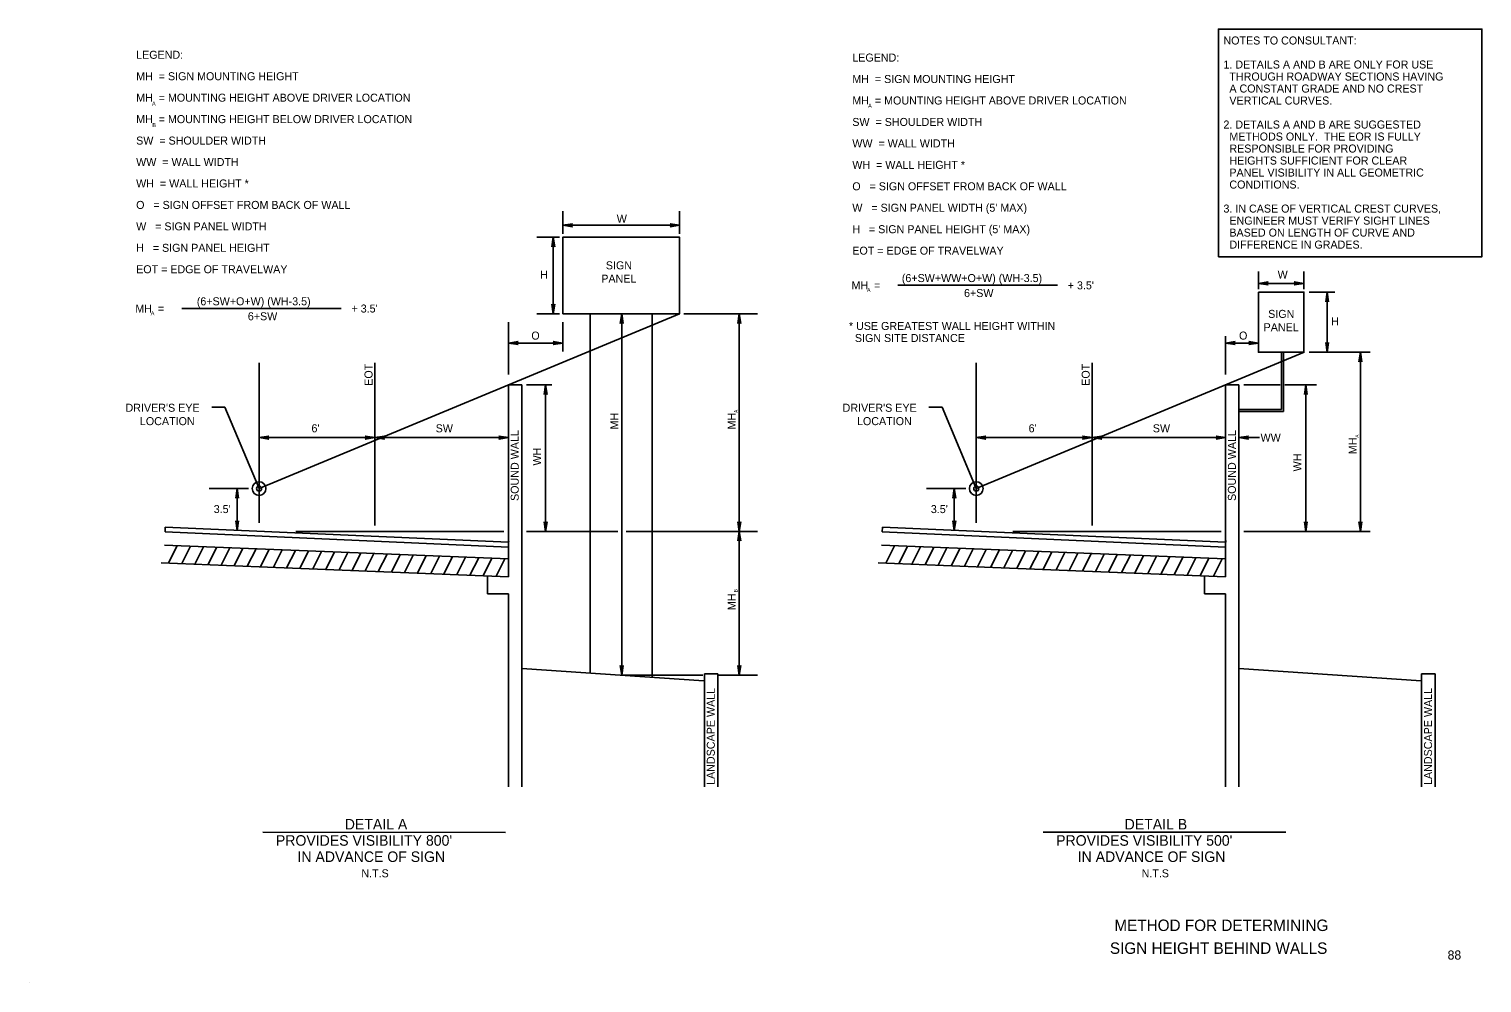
# Model space of a CAD drawing. Extents: x -863 to -227, y -614 to -197.
import ezdxf

# ---------------------------------------------------------------- set-up
doc = ezdxf.new("R2010")
doc.units = 0
for name, color, linetype in [('AdhocPoint_dp', 7, 'Continuous'), ('AsphaltMisc', 7, 'Continuous'), ('Base_px', 7, 'Continuous'), ('DimLines_dp', 7, 'Continuous'), ('TextAlert', 7, 'Continuous'), ('TextDetails', 7, 'Continuous'), ('TextGeotech', 7, 'Continuous'), ('TextLabel', 7, 'Continuous'), ('TextMisc', 7, 'Continuous'), ('TextNotes', 7, 'Continuous'), ('TextShtNo', 7, 'Continuous')]:
    doc.layers.add(name, color=color, linetype=linetype)

msp = doc.modelspace()

# ---------------------------------------------------------------- linework, layer by layer
at = {"layer": 'AdhocPoint_dp'}
msp.add_line((-862.51, -614.11), (-862.51, -614.11), dxfattribs=at)
at = {"layer": 'AsphaltMisc'}
for p, q in [((-802.9, -414.8), (-802.96, -416.83)), ((-802.96, -416.83), (-652.79, -423.57)), ((-652.79, -421.4), (-802.9, -414.8)), ((-489.2, -414.82), (-489.27, -416.84)), ((-489.27, -416.84), (-339.06, -423.58)), ((-339.06, -421.41), (-489.2, -414.82)), ((-652.79, -423.57), (-652.79, -421.4)), ((-339.06, -423.58), (-339.06, -421.41))]:
    msp.add_line(p, q, dxfattribs=at)
at = {"layer": 'Base_px'}
for p, q in [((-577.91, -321.45), (-761.88, -397.92)), ((-617.03, -478.62), (-617.03, -321.45)), ((-589.93, -480.42), (-589.93, -321.45)), ((-304.74, -338.3), (-448.17, -397.92)), ((-314.68, -363.31), (-314.68, -338.3)), ((-313.77, -364.22), (-313.77, -338.3)), ((-652.79, -436.45), (-652.79, -352.57)), ((-652.79, -352.57), (-647, -352.57)), ((-647, -528.36), (-647, -352.57)), ((-339.06, -436.47), (-339.06, -352.57)), ((-339.06, -352.57), (-333.26, -352.57)), ((-333.26, -528.4), (-333.26, -352.57)), ((-333.26, -363.31), (-314.68, -363.31)), ((-333.26, -364.22), (-313.77, -364.22)), ((-803.27, -422.64), (-711.23, -426.32)), ((-801.48, -430.51), (-797.66, -422.87)), ((-795.74, -430.74), (-791.92, -423.1)), ((-790, -430.97), (-786.18, -423.33)), ((-784.26, -431.2), (-780.44, -423.56)), ((-778.52, -431.43), (-774.7, -423.78)), ((-772.78, -431.66), (-768.96, -424.01)), ((-767.04, -431.88), (-763.22, -424.24)), ((-761.3, -432.11), (-757.48, -424.47)), ((-755.57, -432.34), (-751.75, -424.7)), ((-749.84, -432.57), (-746.02, -424.93)), ((-744.11, -432.8), (-740.29, -425.16)), ((-738.38, -433.03), (-734.56, -425.39)), ((-732.65, -433.26), (-728.83, -425.62)), ((-489.58, -422.65), (-397.51, -426.34)), ((-487.78, -430.52), (-483.96, -422.88)), ((-482.04, -430.75), (-478.22, -423.11)), ((-476.3, -430.98), (-472.48, -423.34)), ((-470.56, -431.21), (-466.74, -423.57)), ((-464.82, -431.44), (-461, -423.8)), ((-459.08, -431.67), (-455.26, -424.03)), ((-453.34, -431.9), (-449.52, -424.26)), ((-447.6, -432.13), (-443.77, -424.49)), ((-441.87, -432.36), (-438.04, -424.72)), ((-436.13, -432.59), (-432.31, -424.94)), ((-430.4, -432.82), (-426.58, -425.17)), ((-424.67, -433.05), (-420.85, -425.4)), ((-418.94, -433.28), (-415.12, -425.63)), ((-804.73, -430.38), (-761.88, -432.09)), ((-761.88, -432.09), (-652.79, -436.45)), ((-726.92, -433.49), (-723.1, -425.85)), ((-721.2, -433.72), (-717.38, -426.08)), ((-715.47, -433.95), (-711.65, -426.31)), ((-711.23, -426.32), (-652.79, -428.66)), ((-709.74, -434.18), (-705.92, -426.54)), ((-704.01, -434.41), (-700.19, -426.77)), ((-698.28, -434.64), (-694.46, -426.99)), ((-692.55, -434.86), (-688.73, -427.22)), ((-686.82, -435.09), (-683, -427.45)), ((-681.09, -435.32), (-677.27, -427.68)), ((-675.36, -435.55), (-671.54, -427.91)), ((-669.63, -435.78), (-665.81, -428.14)), ((-663.9, -436.01), (-660.08, -428.37)), ((-658.17, -436.24), (-654.35, -428.6)), ((-491.04, -430.39), (-448.17, -432.11)), ((-448.17, -432.11), (-339.06, -436.47)), ((-413.21, -433.5), (-409.39, -425.86)), ((-407.48, -433.73), (-403.66, -426.09)), ((-401.75, -433.96), (-397.93, -426.32)), ((-397.51, -426.34), (-339.06, -428.68)), ((-396.02, -434.19), (-392.2, -426.55)), ((-390.29, -434.42), (-386.47, -426.78)), ((-384.56, -434.65), (-380.74, -427.01)), ((-378.83, -434.88), (-375, -427.24)), ((-373.09, -435.11), (-369.27, -427.47)), ((-367.36, -435.34), (-363.54, -427.7)), ((-361.63, -435.57), (-357.81, -427.92)), ((-355.9, -435.8), (-352.08, -428.15)), ((-350.17, -436.03), (-346.35, -428.38)), ((-344.44, -436.26), (-340.62, -428.61)), ((-661.99, -432.19), (-661.99, -432.19)), ((-661.99, -432.19), (-661.99, -432.19)), ((-661.99, -436.09), (-661.99, -443.98)), ((-348.26, -432.2), (-348.26, -432.2)), ((-348.26, -432.2), (-348.26, -432.2)), ((-348.26, -436.1), (-348.26, -444)), ((-661.99, -443.98), (-652.79, -443.98)), ((-652.79, -443.98), (-652.79, -528.36)), ((-348.26, -444), (-339.06, -444)), ((-339.06, -444), (-339.06, -528.4)), ((-647, -476.64), (-567.31, -481.92)), ((-333.26, -476.66), (-253.55, -481.95)), ((-567.07, -528.36), (-567.07, -478.86)), ((-567.07, -478.86), (-561.18, -478.86)), ((-561.18, -528.36), (-561.18, -478.86)), ((-253.32, -528.4), (-253.32, -478.88)), ((-253.32, -478.88), (-247.42, -478.88)), ((-247.42, -528.4), (-247.42, -478.88))]:
    msp.add_line(p, q, dxfattribs=at)
for points in [[(-629.05, -321.45), (-577.91, -321.45), (-577.91, -287.99), (-629.05, -287.99)], [(-324.74, -312), (-304.86, -312), (-304.86, -338.3), (-324.74, -338.3)]]:
    msp.add_lwpolyline(points, close=True, dxfattribs=at)
for centre in [(-652.55, -421.4), (-338.81, -421.41)]:
    msp.add_ellipse(centre, major_axis=(0, 0.487), ratio=0.5, start_param=6.189709, end_param=7.853982, dxfattribs=at)
at = {"layer": 'DimLines_dp'}
for p, q in [((-629.05, -286.53), (-629.05, -276.59)), ((-577.91, -286.53), (-577.91, -276.59)), ((-624.84, -282.15), (-629.05, -282.78)), ((-577.91, -282.78), (-629.05, -282.78)), ((-629.05, -282.78), (-624.84, -283.41)), ((-625.68, -282.78), (-624.84, -282.15)), ((-624.84, -283.41), (-625.68, -282.78)), ((-577.91, -282.78), (-582.12, -282.15)), ((-582.12, -282.15), (-581.28, -282.78)), ((-581.28, -282.78), (-582.12, -283.41)), ((-582.12, -283.41), (-577.91, -282.78)), ((-630.5, -287.99), (-640.44, -287.99)), ((-633.17, -287.99), (-633.8, -292.19)), ((-633.8, -292.19), (-633.17, -291.35)), ((-633.17, -321.45), (-633.17, -287.99)), ((-632.54, -292.19), (-633.17, -287.99)), ((-633.17, -291.35), (-632.54, -292.19)), ((-324.74, -310.7), (-324.74, -302.97)), ((-304.86, -310.7), (-304.86, -302.97)), ((-320.53, -307.54), (-324.74, -308.17)), ((-304.86, -308.17), (-324.74, -308.17)), ((-324.74, -308.17), (-320.53, -308.8)), ((-321.37, -308.17), (-320.53, -307.54)), ((-320.53, -308.8), (-321.37, -308.17)), ((-304.86, -308.17), (-309.07, -307.54)), ((-309.07, -307.54), (-308.23, -308.17)), ((-308.23, -308.17), (-309.07, -308.8)), ((-309.07, -308.8), (-304.86, -308.17)), ((-633.17, -318.08), (-633.8, -317.24)), ((-633.8, -317.24), (-633.17, -321.45)), ((-633.17, -321.45), (-632.54, -317.24)), ((-632.54, -317.24), (-633.17, -318.08)), ((-291.36, -312), (-302.53, -312)), ((-294.65, -312), (-295.28, -316.2)), ((-295.28, -316.2), (-294.65, -315.36)), ((-294.65, -338.3), (-294.65, -312)), ((-294.02, -316.2), (-294.65, -312)), ((-294.65, -315.36), (-294.02, -316.2)), ((-630.5, -321.45), (-640.44, -321.45)), ((-603.23, -321.45), (-603.86, -325.65)), ((-603.23, -479.54), (-603.23, -321.45)), ((-602.6, -325.65), (-603.23, -321.45)), ((-576.08, -321.45), (-543.91, -321.45)), ((-551.81, -321.45), (-552.45, -325.65)), ((-551.81, -416.61), (-551.81, -321.45)), ((-551.18, -325.65), (-551.81, -321.45)), ((-652.79, -348.05), (-652.79, -325.2)), ((-629.05, -325.2), (-629.05, -338.03)), ((-603.86, -325.65), (-603.23, -324.81)), ((-603.23, -324.81), (-602.6, -325.65)), ((-552.45, -325.65), (-551.81, -324.81)), ((-551.81, -324.81), (-551.18, -325.65)), ((-648.58, -333.64), (-652.79, -334.27)), ((-629.05, -334.27), (-652.79, -334.27)), ((-652.79, -334.27), (-648.58, -334.9)), ((-649.43, -334.27), (-648.58, -333.64)), ((-648.58, -334.9), (-649.43, -334.27)), ((-629.05, -334.27), (-633.25, -333.64)), ((-633.25, -333.64), (-632.41, -334.27)), ((-632.41, -334.27), (-633.25, -334.9)), ((-633.25, -334.9), (-629.05, -334.27)), ((-339.06, -348.04), (-339.06, -331.19)), ((-334.85, -333.63), (-339.06, -334.26)), ((-324.74, -334.26), (-339.06, -334.26)), ((-339.06, -334.26), (-334.85, -334.89)), ((-335.69, -334.26), (-334.85, -333.63)), ((-334.85, -334.89), (-335.69, -334.26)), ((-324.74, -334.26), (-328.95, -333.63)), ((-328.95, -333.63), (-328.11, -334.26)), ((-328.11, -334.26), (-328.95, -334.89)), ((-328.95, -334.89), (-324.74, -334.26)), ((-294.65, -334.93), (-295.28, -334.09)), ((-295.28, -334.09), (-294.65, -338.3)), ((-294.65, -338.3), (-294.02, -334.09)), ((-294.02, -334.09), (-294.65, -334.93)), ((-761.88, -412.85), (-761.88, -342.91)), ((-711.23, -414.1), (-711.23, -342.91)), ((-448.17, -412.86), (-448.17, -342.9)), ((-397.51, -414.11), (-397.51, -342.9)), ((-275.88, -338.3), (-302.53, -338.3)), ((-280.11, -338.3), (-280.74, -342.51)), ((-280.74, -342.51), (-280.11, -341.67)), ((-280.11, -416.62), (-280.11, -338.3)), ((-279.48, -342.51), (-280.11, -338.3)), ((-280.11, -341.67), (-279.48, -342.51)), ((-633.8, -352.57), (-644.87, -352.57)), ((-636.53, -352.57), (-637.17, -356.78)), ((-636.53, -416.61), (-636.53, -352.57)), ((-635.9, -356.78), (-636.53, -352.57)), ((-315.2, -352.57), (-331.13, -352.57)), ((-299.28, -352.57), (-313.21, -352.57)), ((-303.99, -352.57), (-304.62, -356.78)), ((-303.99, -416.62), (-303.99, -352.57)), ((-303.35, -356.78), (-303.99, -352.57)), ((-637.17, -356.78), (-636.53, -355.94)), ((-636.53, -355.94), (-635.9, -356.78)), ((-304.62, -356.78), (-303.99, -355.93)), ((-303.99, -355.93), (-303.35, -356.78)), ((-782.61, -362.37), (-776.82, -362.37)), ((-776.82, -362.37), (-761.88, -397.92)), ((-468.91, -362.37), (-463.12, -362.37)), ((-463.12, -362.37), (-448.17, -397.92)), ((-757.67, -375), (-761.88, -375.64)), ((-761.88, -375.64), (-757.67, -376.27)), ((-761.88, -375.64), (-652.79, -375.64)), ((-758.51, -375.64), (-757.67, -375)), ((-757.67, -376.27), (-758.51, -375.64)), ((-714.6, -375.64), (-715.44, -375)), ((-715.44, -375), (-711.23, -375.64)), ((-711.23, -375.64), (-715.44, -376.27)), ((-715.44, -376.27), (-714.6, -375.64)), ((-707.02, -375), (-711.23, -375.64)), ((-711.23, -375.64), (-707.02, -376.27)), ((-707.87, -375.64), (-707.02, -375)), ((-707.02, -376.27), (-707.87, -375.64)), ((-652.79, -375.64), (-657, -375)), ((-657, -375), (-656.16, -375.64)), ((-656.16, -375.64), (-657, -376.27)), ((-657, -376.27), (-652.79, -375.64)), ((-443.96, -375), (-448.17, -375.64)), ((-448.17, -375.64), (-443.96, -376.27)), ((-448.17, -375.64), (-339.06, -375.64)), ((-444.81, -375.64), (-443.96, -375)), ((-443.96, -376.27), (-444.81, -375.64)), ((-400.88, -375.64), (-401.72, -375)), ((-401.72, -375), (-397.51, -375.64)), ((-397.51, -375.64), (-401.72, -376.27)), ((-401.72, -376.27), (-400.88, -375.64)), ((-393.3, -375), (-397.51, -375.64)), ((-397.51, -375.64), (-393.3, -376.27)), ((-394.15, -375.64), (-393.3, -375)), ((-393.3, -376.27), (-394.15, -375.64)), ((-339.06, -375.64), (-343.27, -375)), ((-343.27, -375), (-342.43, -375.64)), ((-342.43, -375.64), (-343.27, -376.27)), ((-343.27, -376.27), (-339.06, -375.64)), ((-329.05, -375), (-333.26, -375.64)), ((-333.26, -375.64), (-324.28, -375.64)), ((-333.26, -375.64), (-329.05, -376.27)), ((-329.89, -375.64), (-329.05, -375)), ((-329.05, -376.27), (-329.89, -375.64)), ((-766.49, -397.92), (-783.7, -397.92)), ((-772.13, -402.13), (-771.5, -397.92)), ((-771.5, -416.19), (-771.5, -397.92)), ((-771.5, -397.92), (-770.86, -402.13)), ((-452.78, -397.92), (-470, -397.92)), ((-458.42, -402.13), (-457.79, -397.92)), ((-457.79, -416.2), (-457.79, -397.92)), ((-457.79, -397.92), (-457.16, -402.13)), ((-771.5, -401.28), (-772.13, -402.13)), ((-770.86, -402.13), (-771.5, -401.28)), ((-457.79, -401.29), (-458.42, -402.13)), ((-457.16, -402.13), (-457.79, -401.29)), ((-771.5, -412.82), (-772.13, -411.98)), ((-772.13, -411.98), (-771.5, -416.19)), ((-771.5, -416.19), (-770.86, -411.98)), ((-770.86, -411.98), (-771.5, -412.82)), ((-636.53, -413.24), (-637.17, -412.4)), ((-637.17, -412.4), (-636.53, -416.61)), ((-636.53, -416.61), (-635.9, -412.4)), ((-635.9, -412.4), (-636.53, -413.24)), ((-551.81, -413.24), (-552.45, -412.4)), ((-552.45, -412.4), (-551.81, -416.61)), ((-551.81, -416.61), (-551.18, -412.4)), ((-551.18, -412.4), (-551.81, -413.24)), ((-457.79, -412.83), (-458.42, -411.99)), ((-458.42, -411.99), (-457.79, -416.2)), ((-457.79, -416.2), (-457.16, -411.99)), ((-457.16, -411.99), (-457.79, -412.83)), ((-303.99, -413.25), (-304.62, -412.41)), ((-304.62, -412.41), (-303.99, -416.62)), ((-303.99, -416.62), (-303.35, -412.41)), ((-303.35, -412.41), (-303.99, -413.25)), ((-280.11, -413.25), (-280.74, -412.41)), ((-280.74, -412.41), (-280.11, -416.62)), ((-280.11, -416.62), (-279.48, -412.41)), ((-279.48, -412.41), (-280.11, -413.25)), ((-654.81, -416.61), (-745.83, -416.61)), ((-604.88, -416.61), (-644.87, -416.61)), ((-543.91, -416.61), (-601.28, -416.61)), ((-551.81, -416.61), (-552.45, -420.82)), ((-551.81, -479.54), (-551.81, -416.61)), ((-551.18, -420.82), (-551.81, -416.61)), ((-341.07, -416.62), (-432.12, -416.62)), ((-275.88, -416.62), (-331.13, -416.62)), ((-552.45, -420.82), (-551.81, -419.97)), ((-551.81, -419.97), (-551.18, -420.82)), ((-603.23, -476.17), (-603.86, -475.33)), ((-603.86, -475.33), (-603.23, -479.54)), ((-603.23, -479.54), (-602.6, -475.33)), ((-602.6, -475.33), (-603.23, -476.17)), ((-551.81, -476.17), (-552.45, -475.33)), ((-552.45, -475.33), (-551.81, -479.54)), ((-551.81, -479.54), (-551.18, -475.33)), ((-551.18, -475.33), (-551.81, -476.17)), ((-567.76, -479.53), (-603.23, -479.53)), ((-543.91, -479.53), (-560.72, -479.53))]:
    msp.add_line(p, q, dxfattribs=at)
for centre, radius in [((-761.88, -397.92), 2.98), ((-761.88, -397.92), 1.12), ((-448.17, -397.92), 2.98), ((-448.17, -397.92), 1.12)]:
    msp.add_circle(centre, radius, dxfattribs=at)
at = {"layer": 'TextAlert'}
msp.add_lwpolyline([(-342.24, -296.54), (-226.95, -296.54), (-226.95, -196.95), (-342.24, -196.95)], close=True, dxfattribs=at)
at = {"layer": 'TextDetails'}
for p, q in [((-760.2, -548.13), (-654.02, -548.31)), ((-418.87, -548.13), (-312.7, -548.13))]:
    msp.add_line(p, q, dxfattribs=at)
at = {"layer": 'TextGeotech'}
for centre in [(-652.55, -421.4), (-338.81, -421.41)]:
    msp.add_ellipse(centre, major_axis=(0, -0.487), ratio=0.5, start_param=2.956245, end_param=4.712389, dxfattribs=at)
at = {"layer": 'TextLabel'}
for p, q in [((-482.4, -309.01), (-412.67, -309.01)), ((-795.69, -319.16), (-725.97, -319.16))]:
    msp.add_line(p, q, dxfattribs=at)

# ---------------------------------------------------------------- texts
at = {"layer": 'DimLines_dp'}
for s, height, p in [('EOT', 3.506, (-712.25, -352.96)), ('EOT', 3.507, (-398.53, -352.95)), ('MH', 3.506, (-604.72, -372.04)), ('MH', 3.506, (-553.38, -372.04)), ('A', 1.5, (-552.6, -364.81)), ('SOUND WALL', 3.506, (-648.31, -403.34)), ('SOUND WALL', 3.507, (-334.58, -403.34)), ('A', 1.5, (-280.89, -375.67)), ('WH', 3.506, (-638.51, -387.82)), ('MH', 3.507, (-281.68, -382.9)), ('WH', 3.507, (-305.96, -390.41)), ('MH', 3.506, (-553.38, -451.09)), ('B', 1.5, (-552.6, -443.28)), ('LANDSCAPE WALL', 3.5064, (-562.54, -527.52)), ('LANDSCAPE WALL', 3.5073, (-248.78, -527.56))]:
    msp.add_text(s, height=height, rotation=90, dxfattribs=at).set_placement(p)
at = {"layer": 'TextAlert'}
for s, p in [('NOTES TO CONSULTANT:', (-340.03, -203.7)), ('1. DETAILS A AND B ARE ONLY FOR USE', (-340.03, -214.2)), ('  THROUGH ROADWAY SECTIONS HAVING', (-340.03, -219.45)), ('  A CONSTANT GRADE AND NO CREST', (-340.03, -224.7)), ('  VERTICAL CURVES.', (-340.03, -229.95)), ('2. DETAILS A AND B ARE SUGGESTED', (-340.03, -240.45)), ('  METHODS ONLY.  THE EOR IS FULLY', (-340.03, -245.7)), ('  RESPONSIBLE FOR PROVIDING', (-340.03, -250.95)), ('  HEIGHTS SUFFICIENT FOR CLEAR ', (-340.03, -256.2)), ('  PANEL VISIBILITY IN ALL GEOMETRIC', (-340.03, -261.45)), ('  CONDITIONS.', (-340.03, -266.7)), ('3. IN CASE OF VERTICAL CREST CURVES,', (-340.03, -277.21)), ('  ENGINEER MUST VERIFY SIGHT LINES', (-340.03, -282.46)), ('  BASED ON LENGTH OF CURVE AND', (-340.03, -287.71)), ('  DIFFERENCE IN GRADES.', (-340.03, -292.96))]:
    msp.add_text(s, height=3.5006, dxfattribs=at).set_placement(p)
at = {"layer": 'TextDetails'}
for s, height, p in [('DETAIL A', 4.6, (-724.4, -547)), ('DETAIL B', 4.6, (-383.24, -547)), ("PROVIDES VISIBILITY 800'", 4.6, (-754.53, -554.1)), ("PROVIDES VISIBILITY 500'", 4.6, (-413.21, -554.1)), ('IN ADVANCE OF SIGN', 4.6, (-745.1, -561.2)), ('IN ADVANCE OF SIGN', 4.6, (-403.78, -561.2)), ('N.T.S', 3.5, (-717.14, -567.91)), ('N.T.S', 3.5, (-375.82, -567.91))]:
    msp.add_text(s, height=height, dxfattribs=at).set_placement(p)
at = {"layer": 'TextLabel'}
for s, height, p in [('(6+SW+WW+O+W) (WH-3.5)', 3.5006, (-480.72, -307.6)), ('MH  = ', 3.501, (-502.73, -310.76)), ('A', 1.75, (-495.99, -311.99)), ('6+SW', 3.501, (-453.51, -314.16)), ("+ 3.5'", 3.501, (-408.15, -310.77)), ('MH  = ', 3.5, (-816.02, -320.91)), ('(6+SW+O+W) (WH-3.5)', 3.4996, (-789.13, -317.75)), ("+ 3.5'", 3.5, (-721.46, -320.92)), ('A', 1.75, (-809.28, -322.14)), ('6+SW', 3.5, (-766.81, -324.31)), ('* USE GREATEST WALL HEIGHT WITHIN', 3.5006, (-503.86, -328.55)), ('  SIGN SITE DISTANCE', 3.5006, (-503.86, -333.8))]:
    msp.add_text(s, height=height, dxfattribs=at).set_placement(p)
at = {"layer": 'TextMisc'}
for s, height, p in [('W', 3.51, (-605.42, -281.68)), ('SIGN', 3.506, (-610.2, -302.03)), ('H', 3.51, (-639, -306.1)), ('PANEL', 3.506, (-612.19, -307.87)), ('W', 3.51, (-316.33, -306.05)), ('SIGN', 3.507, (-320.47, -323.27)), ('H', 3.51, (-292.91, -326.57)), ('O', 3.51, (-642.79, -332.77)), ('O', 3.51, (-333.2, -332.76)), ('PANEL', 3.507, (-322.46, -329.11)), ("DRIVER'S EYE", 3.5064, (-820.32, -364.32)), ("DRIVER'S EYE", 3.5073, (-506.63, -364.32)), ('LOCATION', 3.506, (-814.03, -370.17)), ('LOCATION', 3.507, (-500.34, -370.17)), ("6'", 3.506, (-738.97, -373.3)), ('SW', 3.506, (-684.64, -373.3)), ("6'", 3.507, (-425.26, -373.3)), ('SW', 3.507, (-370.92, -373.3)), ('WW', 3.507, (-323.8, -377.37)), ("3.5'", 3.506, (-781.73, -408.62)), ("3.5'", 3.507, (-468.03, -408.63))]:
    msp.add_text(s, height=height, dxfattribs=at).set_placement(p)
for s, p in [(' METHOD FOR DETERMINING ', (-389.61, -591.4)), ('SIGN HEIGHT BEHIND WALLS', (-389.7, -601.4))]:
    msp.add_text(s, height=5, rotation=360, dxfattribs=at).set_placement(p)
at = {"layer": 'TextNotes'}
for s, height, p in [('LEGEND:', 3.5, (-815.66, -209.95)), ('LEGEND:', 3.501, (-502.38, -211.17)), ('MH  = SIGN MOUNTING HEIGHT', 3.4996, (-815.66, -219.33)), ('MH  = SIGN MOUNTING HEIGHT', 3.5006, (-502.38, -220.55)), ('MH  = MOUNTING HEIGHT ABOVE DRIVER LOCATION', 3.4996, (-815.66, -228.71)), ('A', 1.75, (-808.75, -230.4)), ('MH  = MOUNTING HEIGHT ABOVE DRIVER LOCATION', 3.5006, (-502.38, -229.94)), ('MH  = MOUNTING HEIGHT BELOW DRIVER LOCATION', 3.4996, (-815.66, -238.09)), ('A', 1.75, (-495.47, -231.35)), ('B', 1.75, (-808.58, -239.82)), ('SW  = SHOULDER WIDTH', 3.5006, (-502.38, -239.32)), ('SW  = SHOULDER WIDTH', 3.4996, (-815.66, -247.47)), ('WW  = WALL WIDTH', 3.5006, (-502.38, -248.7)), ('WW  = WALL WIDTH', 3.4996, (-815.66, -256.85)), ('WH  = WALL HEIGHT *', 3.5006, (-502.38, -258.08)), ('WH  = WALL HEIGHT *', 3.4996, (-815.66, -266.23)), ('O   = SIGN OFFSET FROM BACK OF WALL', 3.5006, (-502.38, -267.46)), ('O   = SIGN OFFSET FROM BACK OF WALL', 3.4996, (-815.66, -275.61)), ("W   = SIGN PANEL WIDTH (5' MAX)", 3.5006, (-502.38, -276.84)), ('W   = SIGN PANEL WIDTH', 3.4996, (-815.66, -284.99)), ("H   = SIGN PANEL HEIGHT (5' MAX)", 3.5006, (-502.38, -286.23)), ('H   = SIGN PANEL HEIGHT', 3.4996, (-815.66, -294.37)), ('EOT = EDGE OF TRAVELWAY', 3.5006, (-502.38, -295.61)), ('EOT = EDGE OF TRAVELWAY', 3.4996, (-815.66, -303.74))]:
    msp.add_text(s, height=height, dxfattribs=at).set_placement(p)
at = {"layer": 'TextShtNo'}
msp.add_text('88', height=4, rotation=360, dxfattribs=at).set_placement((-241.97, -603.9))

doc.saveas('drawing.dxf')
